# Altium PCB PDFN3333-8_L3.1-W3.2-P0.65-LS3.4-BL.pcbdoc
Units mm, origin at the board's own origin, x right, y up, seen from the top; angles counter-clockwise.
Board outline 15.93 x 16.92 mm, 2 copper layers (Top Layer, Bottom Layer), stack 0.07 mm thick; 1 components, 0 nets, 9 pads, 0 vias.
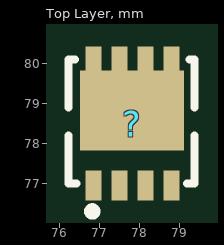
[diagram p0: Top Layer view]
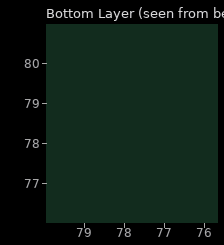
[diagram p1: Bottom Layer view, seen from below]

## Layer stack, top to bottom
Top Solder Mask Layer: solder mask 0.01, Dk 3.3
Top Layer: signal copper 0.035
Bottom Layer: signal copper 0.035
Bottom Solder Mask Layer: solder mask 0.01, Dk 3.3

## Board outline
85.78,69.85 69.85,69.85 69.85,86.775 85.78,86.775

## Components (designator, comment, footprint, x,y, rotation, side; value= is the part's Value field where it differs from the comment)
? "PDFN3333-8_L3.1-W3.2-P0.65-LS3.4-BL" PDFN3333-8_L3.1-W3.2-P0.65-LS3.4-BL 77.83,78.491 r0 top

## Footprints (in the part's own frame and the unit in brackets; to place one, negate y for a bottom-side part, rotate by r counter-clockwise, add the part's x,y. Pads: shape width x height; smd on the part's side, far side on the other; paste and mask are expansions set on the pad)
PDFN3333-8_L3.1-W3.2-P0.65-LS3.4-BL [mm]
  rect 0.4x0.75 smd paste-100 mask+0.051: 1(-0.975,-1.533) 2(-0.325,-1.533) 3(0.325,-1.533) 4(0.975,-1.533)
  rect 0.4x0.8 smd paste-100 mask+0.051: 5(0.975,1.533) 6(0.325,1.533) 7(-0.325,1.533) 8(-0.975,1.533)
  rect 2.6x2 smd paste-100 mask+0.051: 9(-0.005,0.333)
  silkscreen extent -1.59,-2.29 1.56,1.61

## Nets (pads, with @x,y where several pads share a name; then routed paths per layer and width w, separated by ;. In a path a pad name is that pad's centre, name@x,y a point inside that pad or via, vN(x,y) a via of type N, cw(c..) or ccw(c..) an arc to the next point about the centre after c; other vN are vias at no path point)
pads on no net: ?.1 ?.2 ?.3 ?.4 ?.5 ?.6 ?.7 ?.8 ?.9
